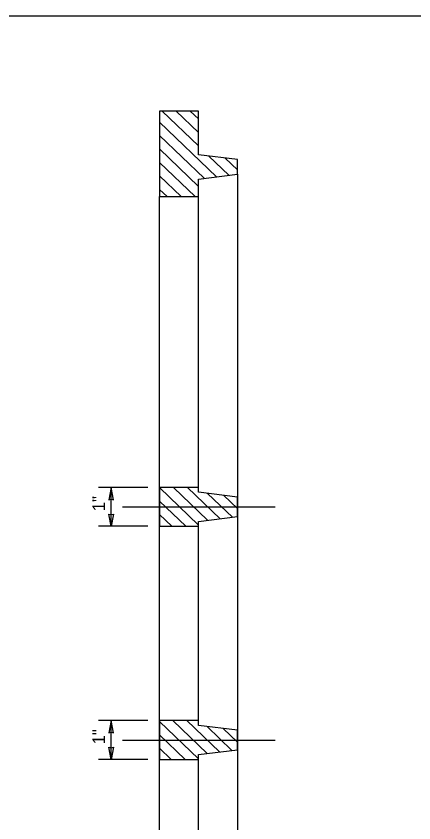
# Model space of a CAD drawing. Extents: x 99862 to 103151, y 100000 to 102076.
# Drawn here: x 101651 to 102163, y 101038 to 102076 of the extents above; entities that cross this region are included whole.
import ezdxf

# ---------------------------------------------------------------- set-up
doc = ezdxf.new("R2010")
doc.units = 0
for name, color, linetype in [('Level 1', 7, 'Continuous'), ('Level 12', 7, 'Continuous'), ('Level 15', 7, 'Continuous'), ('Level 18', 7, 'Continuous'), ('Level 20', 7, 'Continuous')]:
    doc.layers.add(name, color=color, linetype=linetype)

msp = doc.modelspace()

# ---------------------------------------------------------------- linework, layer by layer
at = {"layer": 'Level 1'}
msp.add_lwpolyline([(99862, 99999.5), (103151, 99999.5), (103151, 102075.5), (99862, 102075.5)], close=True, dxfattribs=at)
at = {"layer": 'Level 12'}
for p, q in [((101885.7, 101908.5), (101838.9, 101953.4)), ((101885.7, 101925.9), (101857, 101953.4)), ((101885.7, 101943.2), (101875, 101953.4)), ((101908.9, 101868.8), (101835.7, 101939.2)), ((101892.9, 101866.9), (101835.7, 101921.9)), ((101885.7, 101856.5), (101835.7, 101904.6)), ((101924.9, 101870.8), (101899.2, 101895.5)), ((101935.7, 101877.8), (101919.9, 101892.9)), ((101881.4, 101843.3), (101835.7, 101887.2)), ((101863.3, 101843.3), (101835.7, 101869.9)), ((101845.3, 101843.3), (101835.7, 101852.5)), ((101885.7, 101420.7), (101835.7, 101468.8)), ((101897.4, 101426.8), (101853.4, 101469.1)), ((101913.4, 101428.8), (101871.5, 101469.1)), ((101929.3, 101430.8), (101897.5, 101461.3)), ((101935.7, 101442), (101918.3, 101458.7)), ((101869.4, 101419.1), (101835.7, 101451.4)), ((101851.3, 101419.1), (101835.7, 101434.1)), ((101885.7, 101120.1), (101835.7, 101168.1)), ((101896.8, 101126.7), (101852.7, 101169.1)), ((101912.8, 101128.7), (101870.8, 101169.1)), ((101928.7, 101130.7), (101896.8, 101161.4)), ((101935.7, 101141.4), (101917.5, 101158.8)), ((101868.7, 101119.1), (101835.7, 101150.8)), ((101850.6, 101119.1), (101835.7, 101133.5))]:
    msp.add_line(p, q, dxfattribs=at)
at = {"layer": 'Level 15'}
for p, q in [((101820.7, 101469.1), (101757.2, 101469.1)), ((101773.2, 101419.1), (101773.2, 101469.1)), ((101787.9, 101444.1), (101984.4, 101444.1)), ((101820.7, 101419.1), (101757.2, 101419.1)), ((101820.7, 101169.1), (101757.2, 101169.1)), ((101773.2, 101119.1), (101773.2, 101169.1)), ((101787.9, 101144.1), (101984.4, 101144.1)), ((101820.7, 101119.1), (101757.2, 101119.1))]:
    msp.add_line(p, q, dxfattribs=at)
for points in [[(101773.2, 101469.1), (101770.1, 101453.3), (101773.2, 101454.1), (101776.3, 101453.3)], [(101773.2, 101419.1), (101770.1, 101434.8), (101773.2, 101434.1), (101776.3, 101434.8)], [(101773.2, 101169.1), (101770.1, 101153.3), (101773.2, 101154.1), (101776.3, 101153.3)], [(101773.2, 101119.1), (101770.1, 101134.8), (101773.2, 101134.1), (101776.3, 101134.8)]]:
    msp.add_lwpolyline(points, close=True, dxfattribs=at)
at = {"layer": 'Level 18'}
for p, q in [((101935.7, 101872.2), (101935.7, 100715.9)), ((101835.7, 100745.5), (101835.7, 101843.3)), ((101885.7, 101469.1), (101885.7, 101843.3)), ((101885.7, 101169.1), (101885.7, 101419.1)), ((101885.7, 100745.5), (101885.7, 101119.1))]:
    msp.add_line(p, q, dxfattribs=at)
for points in [[(101835.7, 101953.4), (101835.7, 101843.3), (101885.7, 101843.3), (101885.7, 101865.9), (101935.7, 101872.2), (101935.7, 101890.9), (101885.7, 101897.2), (101885.7, 101953.4), (101835.7, 101953.4)], [(101885.7, 101462.8), (101885.7, 101469.1), (101835.7, 101469.1), (101835.7, 101419.1), (101885.7, 101419.1), (101885.7, 101425.3), (101935.7, 101431.6), (101935.7, 101456.6), (101885.7, 101462.8)], [(101885.7, 101162.8), (101885.7, 101169.1), (101835.7, 101169.1), (101835.7, 101119.1), (101885.7, 101119.1), (101885.7, 101125.3), (101935.7, 101131.6), (101935.7, 101156.6), (101885.7, 101162.8)]]:
    msp.add_lwpolyline(points, dxfattribs=at)

# ---------------------------------------------------------------- texts
at = {"layer": 'Level 20'}
for p in [(101765.2, 101438.5), (101765.2, 101138.5)]:
    msp.add_text('1"', height=16, rotation=90, dxfattribs=at).set_placement(p)

doc.saveas('drawing.dxf')
